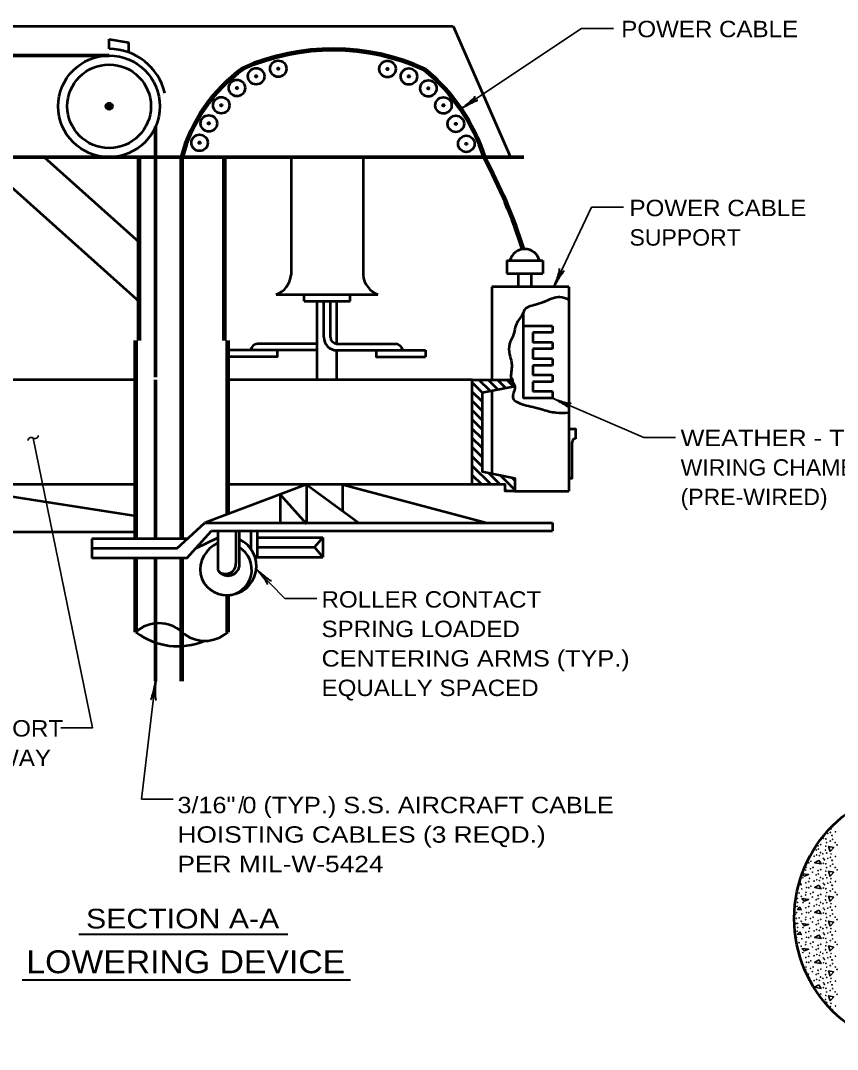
# Model space of a CAD drawing. Extents: x -1 to 679, y 0 to 440.
# Drawn here: x 208.2 to 332.8, y 109.6 to 266.6 of the extents above; entities that cross this region are included whole.
import ezdxf
from ezdxf.enums import TextEntityAlignment as Align

# ---------------------------------------------------------------- set-up
doc = ezdxf.new("R2010")
doc.units = 0
doc.header["$PDMODE"] = 32
doc.header["$PDSIZE"] = 0.5
doc.layers.add('1', color=7, linetype='Continuous', lineweight=35)

msp = doc.modelspace()

# ---------------------------------------------------------------- hatches: boundary and pattern name
at = {"layer": '1'}
for points in [[(247.661, 259.304, 1), (247.411, 259.304, 1)], [(264.325, 259.26, 1), (264.075, 259.26, 1)], [(244.293, 258.151, 1), (244.043, 258.151, 1)], [(267.586, 258.116, 1), (267.336, 258.116, 1)], [(241.357, 256.358, 1), (241.107, 256.358, 1)], [(270.557, 256.295, 1), (270.307, 256.295, 1)], [(222.233, 253.567, 1), (221.233, 253.567, 1)], [(238.965, 253.726, 1), (238.715, 253.726, 1)], [(272.86, 253.701, 1), (272.61, 253.701, 1)], [(237.069, 250.956, 1), (236.819, 250.956, 1)], [(274.748, 250.886, 1), (274.498, 250.886, 1)], [(235.657, 247.993, 1), (235.407, 247.993, 1)], [(276.345, 247.833, 1), (276.095, 247.833, 1)]]:
    msp.add_hatch(color=256, dxfattribs=at).paths.add_polyline_path(points)

# ---------------------------------------------------------------- linework, layer by layer
at = {"layer": '1', "lineweight": 53}
for p, q in [((194.233, 265.817), (274.233, 265.817)), ((274.233, 265.817), (282.983, 245.817)), ((221.733, 262.317), (221.733, 263.817)), ((221.733, 263.817), (224.733, 263.317)), ((224.733, 261.787), (224.733, 263.317)), ((201.721, 245.817), (226.335, 223.749)), ((211.835, 245.817), (226.335, 232.817)), ((249.483, 245.817), (249.483, 227.817)), ((260.483, 245.817), (260.483, 227.817)), ((282.378, 230.022), (287.878, 230.022)), ((282.378, 230.022), (282.378, 228.022)), ((287.878, 230.022), (287.878, 228.022)), ((282.378, 228.022), (287.878, 228.022)), ((284.128, 228.022), (284.128, 226.022)), ((286.128, 228.022), (286.128, 226.022)), ((247.233, 224.817), (262.733, 224.817)), ((251.483, 223.817), (251.483, 224.817)), ((258.483, 223.817), (258.483, 224.817)), ((291.878, 226.022), (280.128, 226.022)), ((280.128, 226.022), (280.128, 211.817)), ((291.878, 226.022), (291.878, 194.817)), ((251.483, 223.817), (258.483, 223.817)), ((253.483, 211.817), (253.483, 223.817)), ((254.483, 218.317), (254.483, 223.817)), ((255.483, 218.317), (255.483, 223.817)), ((256.483, 217.317), (256.483, 223.817)), ((284.878, 222.022), (284.878, 209.022)), ((289.378, 220.022), (284.878, 220.022)), ((289.378, 220.022), (289.378, 219.022)), ((289.378, 219.022), (286.378, 219.022)), ((286.378, 219.022), (286.378, 217.522)), ((253.483, 217.317), (244.353, 217.317)), ((256.483, 217.317), (265.483, 217.317)), ((289.378, 217.522), (286.378, 217.522)), ((289.378, 217.522), (289.378, 216.522)), ((239.853, 216.317), (239.853, 215.317)), ((253.483, 216.317), (239.853, 216.317)), ((256.483, 216.317), (269.983, 216.317)), ((256.483, 211.817), (256.483, 216.317)), ((269.983, 216.317), (269.983, 215.317)), ((289.378, 216.522), (286.378, 216.522)), ((286.378, 216.522), (286.378, 215.022)), ((289.378, 215.022), (286.378, 215.022)), ((289.378, 214.022), (286.378, 214.022)), ((286.378, 214.022), (286.378, 212.522)), ((289.378, 215.022), (289.378, 214.022)), ((289.378, 212.522), (286.378, 212.522)), ((289.378, 212.522), (289.378, 211.522)), ((225.835, 211.817), (196.233, 211.817)), ((277.128, 211.817), (239.835, 211.817)), ((278.707, 209.833), (277.128, 211.412)), ((279.886, 210.069), (278.137, 211.817)), ((281.064, 210.304), (279.552, 211.817)), ((282.243, 210.54), (280.966, 211.817)), ((283.421, 210.776), (282.38, 211.817)), ((289.378, 211.522), (286.378, 211.522)), ((286.378, 211.522), (286.378, 210.022)), ((278.628, 208.498), (277.128, 209.998)), ((280.128, 210.117), (280.128, 197.517)), ((289.378, 209.022), (284.878, 209.022)), ((289.378, 210.022), (286.378, 210.022)), ((289.378, 210.022), (289.378, 209.022)), ((278.628, 207.084), (277.128, 208.584)), ((278.628, 205.67), (277.128, 207.17)), ((278.628, 204.256), (277.128, 205.756)), ((278.628, 202.841), (277.128, 204.341)), ((278.628, 201.427), (277.128, 202.927)), ((278.628, 200.013), (277.128, 201.513)), ((278.628, 198.599), (277.128, 200.099)), ((279.995, 195.817), (277.128, 198.684)), ((278.581, 195.817), (277.128, 197.27)), ((281.409, 195.817), (279.605, 197.622)), ((283.628, 195.013), (281.373, 197.268)), ((283.628, 196.427), (283.14, 196.915)), ((195.233, 195.817), (225.835, 191.067)), ((225.835, 195.817), (196.233, 195.817)), ((251.835, 195.817), (236.335, 190.005)), ((277.128, 195.817), (239.835, 195.817)), ((251.835, 195.817), (251.835, 189.817)), ((251.835, 195.817), (259.828, 190.005)), ((257.335, 195.817), (257.335, 191.817)), ((257.335, 195.817), (279.328, 190.005)), ((277.167, 195.817), (277.128, 195.856)), ((282.409, 194.817), (282.128, 195.099)), ((283.628, 194.817), (291.878, 194.817)), ((247.835, 194.317), (247.835, 189.817)), ((247.835, 194.317), (251.835, 189.817)), ((225.835, 188.567), (164.733, 188.567)), ((232.085, 186.067), (236.335, 190.005)), ((233.585, 184.567), (237.335, 188.755)), ((236.335, 190.005), (289.378, 190.005)), ((237.335, 188.755), (289.378, 188.755)), ((238.335, 188.755), (238.335, 182.755)), ((241.085, 188.755), (241.085, 183.755)), ((241.585, 188.755), (241.585, 183.255)), ((243.335, 188.755), (243.335, 186.092)), ((244.335, 188.755), (244.335, 184.755)), ((289.378, 190.005), (289.378, 188.755)), ((233.704, 187.567), (219.085, 187.567)), ((219.085, 187.567), (219.085, 184.567)), ((238.335, 187.709), (234.878, 186.01)), ((244.335, 187.755), (254.335, 187.755)), ((254.335, 187.755), (254.335, 184.755)), ((232.085, 186.067), (219.085, 186.067)), ((244.335, 186.255), (253.085, 186.255)), ((233.585, 184.567), (219.085, 184.567)), ((244.016, 184.755), (254.335, 184.755))]:
    msp.add_line(p, q, dxfattribs=at)
at = {"layer": '1'}
for p, q in [((275.388, 253.162), (293.808, 265.43)), ((298.666, 265.43), (293.808, 265.43)), ((289.577, 226.022), (295.324, 238.144)), ((300.181, 238.144), (295.324, 238.144)), ((289.378, 209.022), (303.279, 203.025)), ((308.137, 203.025), (303.279, 203.025)), ((244.191, 182.927), (248.548, 178.457)), ((253.405, 178.457), (248.548, 178.457)), ((228.835, 165.817), (226.651, 147.826)), ((231.508, 147.826), (226.651, 147.826)), ((327.108, 135.18), (327.029, 135.097))]:
    msp.add_line(p, q, dxfattribs=at)
at = {"layer": '1', "lineweight": 70}
for p, q in [((200.233, 261.317), (221.733, 261.317)), ((228.835, 212.197), (228.835, 250.466)), ((239.335, 245.817), (284.983, 245.817)), ((228.835, 187.567), (228.835, 211.815)), ((228.835, 165.817), (228.835, 184.567))]:
    msp.add_line(p, q, dxfattribs=at)
at = {"layer": '1', "lineweight": 200}
for p, q in [((226.335, 217.817), (226.335, 245.817)), ((232.835, 187.567), (232.835, 245.817)), ((239.335, 217.817), (239.335, 245.817)), ((225.835, 187.567), (225.835, 217.817)), ((239.835, 191.317), (239.835, 217.817)), ((225.835, 173.317), (225.835, 184.567)), ((232.835, 165.817), (232.835, 184.567)), ((239.835, 173.317), (239.835, 178.92))]:
    msp.add_line(p, q, dxfattribs=at)
at = {"layer": '1', "lineweight": 40}
for p, q in [((217.135, 127.196), (248.977, 127.196)), ((208.484, 120.206), (258.561, 120.206))]:
    msp.add_line(p, q, dxfattribs=at)
at = {"layer": '1', "lineweight": 70}
msp.add_lwpolyline([(183.483, 245.817), (228.835, 245.817), (239.335, 245.817)], dxfattribs=at)
at = {"layer": '1', "lineweight": 53}
for points in [[(247.353, 216.317), (247.353, 215.317), (239.853, 215.317)], [(262.483, 216.317), (262.483, 215.317), (269.983, 215.317)], [(277.128, 195.817), (277.128, 211.817), (283.128, 211.817)], [(283.628, 210.817), (278.628, 209.817), (278.628, 197.817), (283.628, 196.817), (283.628, 194.817), (282.128, 194.817), (282.128, 195.817), (277.128, 195.817)], [(291.878, 204.317), (292.878, 204.317), (292.878, 202.817)], [(291.878, 196.817), (292.378, 196.817), (292.378, 202.317)], [(254.335, 187.755), (253.085, 186.255), (254.335, 184.755)]]:
    msp.add_lwpolyline(points, dxfattribs=at)
at = {"layer": '1'}
for points in [[(210.138, 202.928), (219.214, 158.699), (214.356, 158.699)], [(331.728, 139.8), (331.488, 140.6), (332.268, 140.44), (331.708, 139.84)], [(330.008, 138.46), (329.348, 138.1), (330.328, 137.92), (329.968, 138.48)], [(331.728, 136), (331.488, 136.8), (332.268, 136.64), (331.708, 136.04)], [(326.94, 134.765), (327.308, 134.74), (327.108, 135.14)], [(327.454, 136.412), (328.428, 136.3), (327.748, 136.06), (327.438, 136.37)], [(330.008, 134.66), (329.348, 134.3), (330.328, 134.12), (329.968, 134.68)], [(331.728, 132.2), (331.488, 133), (332.268, 132.84), (331.708, 132.24)], [(327.108, 131.38), (326.728, 130.98), (327.308, 130.94), (327.108, 131.34)], [(330.008, 130.86), (329.348, 130.5), (330.328, 130.32), (329.968, 130.88)], [(331.728, 128.4), (331.488, 129.2), (332.268, 129.04), (331.708, 128.44)], [(327.108, 127.58), (326.728, 127.18), (327.308, 127.14), (327.108, 127.54)], [(330.008, 127.06), (329.348, 126.7), (330.328, 126.52), (329.968, 127.08)], [(331.728, 124.6), (331.488, 125.4), (332.268, 125.24), (331.708, 124.64)], [(327.247, 123.344), (327.308, 123.34), (327.157, 123.641)], [(330.008, 123.26), (329.348, 122.9), (330.328, 122.72), (329.968, 123.28)], [(328.138, 121.133), (328.428, 121.1), (328.197, 121.018)], [(331.728, 120.8), (331.488, 121.6), (332.268, 121.44), (331.708, 120.84)], [(330.008, 119.46), (329.348, 119.1), (330.328, 118.92), (329.968, 119.48)], [(331.728, 117), (331.488, 117.8), (332.268, 117.64), (331.708, 117.04)]]:
    msp.add_lwpolyline(points, dxfattribs=at)
for points in [[(327.388, 132.62), (328.428, 132.5), (327.748, 132.26)], [(327.388, 128.82), (328.428, 128.7), (327.748, 128.46)], [(327.388, 125.02), (328.428, 124.9), (327.748, 124.66)]]:
    msp.add_lwpolyline(points, close=True, dxfattribs=at)
at = {"layer": '1', "lineweight": 53}
for centre, radius in [((221.733, 253.567), 7.75), ((221.733, 253.567), 6.375), ((244.168, 258.151), 1.25), ((247.536, 259.304), 1.25), ((247.536, 259.304), 0.125), ((264.2, 259.26), 1.25), ((264.2, 259.26), 0.125), ((267.461, 258.116), 1.25), ((241.232, 256.358), 1.25), ((244.168, 258.151), 0.125), ((267.461, 258.116), 0.125), ((241.232, 256.358), 0.125), ((270.432, 256.295), 1.25), ((270.432, 256.295), 0.125), ((238.84, 253.726), 1.25), ((272.735, 253.701), 1.25), ((221.733, 253.567), 0.5), ((238.84, 253.726), 0.125), ((272.735, 253.701), 0.125), ((236.944, 250.956), 1.25), ((274.623, 250.886), 1.25), ((236.944, 250.956), 0.125), ((274.623, 250.886), 0.125), ((235.532, 247.993), 1.25), ((276.22, 247.833), 1.25), ((235.532, 247.993), 0.125), ((276.22, 247.833), 0.125), ((346.236, 129.608), 20)]:
    msp.add_circle(centre, radius, dxfattribs=at)
at = {"layer": '1'}
for centre in [(331.849, 143.256), (330.683, 141.829), (331.067, 141.737), (331.359, 142.572), (331.73, 141.405), (331.756, 142.731), (331.982, 142.267), (332.035, 142.267), (332.101, 141.684), (332.538, 142.837), (329.596, 140.053), (329.874, 140.689), (329.914, 140.199), (330.285, 140.862), (331.014, 140.026), (331.054, 140.623), (331.187, 141.167), (332.499, 141.193), (332.777, 140.822), (328.774, 138.321), (329.265, 139.103), (329.662, 139.297), (330.06, 139.17), (330.259, 139.655), (330.617, 139.456), (330.683, 138.772), (330.842, 138.56), (331.2, 139.602), (331.359, 138.772), (331.756, 138.931), (331.849, 139.456), (331.982, 138.467), (332.035, 138.467), (332.538, 139.037), (327.979, 136.995), (328.032, 137.393), (328.456, 138.083), (328.721, 137.181), (329, 136.664), (329.119, 137.393), (329.874, 136.889), (330.285, 137.062), (330.683, 138.029), (331.054, 136.823), (331.067, 137.937), (331.187, 137.367), (331.73, 137.605), (332.101, 137.884), (332.499, 137.393), (332.777, 137.022), (327.569, 135.802), (328.006, 135.038), (328.456, 135.21), (328.562, 135.723), (329.265, 135.303), (329.596, 136.253), (329.662, 135.497), (329.914, 136.399), (330.06, 135.37), (330.259, 135.855), (330.617, 135.656), (331.014, 136.226), (331.2, 135.802), (331.756, 135.131), (331.849, 135.656), (332.538, 135.237), (326.972, 133.487), (327.396, 134.097), (328.032, 133.593), (328.112, 134.322), (328.456, 134.283), (328.774, 134.521), (329.119, 133.593), (330.683, 134.972), (330.683, 134.229), (330.842, 134.76), (331.067, 134.137), (331.187, 133.567), (331.359, 134.972), (331.73, 133.805), (331.982, 134.667), (332.035, 134.667), (332.101, 134.084), (332.499, 133.593), (326.534, 132.623), (326.76, 132.639), (326.76, 132.042), (327.303, 132.97), (327.569, 132.002), (327.979, 133.195), (328.562, 131.923), (328.721, 133.381), (329, 132.864), (329.596, 132.453), (329.874, 133.089), (329.914, 132.599), (330.259, 132.055), (330.285, 133.262), (331.014, 132.426), (331.054, 133.023), (331.2, 132.002), (332.777, 133.222), (326.381, 130.549), (326.614, 130.469), (326.667, 131.45), (328.006, 131.238), (328.112, 130.522), (328.456, 131.41), (328.456, 130.483), (328.774, 130.721), (329.265, 131.503), (329.662, 131.697), (330.06, 131.57), (330.617, 131.856), (330.683, 131.172), (330.683, 130.429), (330.842, 130.96), (331.067, 130.337), (331.359, 131.172), (331.756, 131.331), (331.849, 131.856), (331.982, 130.867), (332.035, 130.867), (332.538, 131.437), (326.395, 130.231), (326.534, 128.823), (326.554, 129.634), (326.76, 128.839), (326.972, 129.687), (327.303, 129.17), (327.396, 130.297), (327.979, 129.395), (328.032, 129.793), (328.721, 129.581), (329, 129.064), (329.119, 129.793), (329.874, 129.289), (329.914, 128.799), (330.285, 129.462), (331.054, 129.223), (331.187, 129.767), (331.73, 130.005), (332.101, 130.284), (332.499, 129.793), (332.777, 129.422), (326.667, 127.65), (326.76, 128.242), (327.569, 128.202), (328.006, 127.438), (328.456, 127.61), (328.562, 128.123), (329.265, 127.703), (329.596, 128.653), (329.662, 127.897), (330.06, 127.77), (330.259, 128.255), (330.617, 128.056), (330.683, 127.372), (331.014, 128.626), (331.2, 128.202), (331.359, 127.372), (331.756, 127.531), (331.849, 128.056), (332.538, 127.637), (326.614, 126.669), (326.972, 125.887), (327.396, 126.497), (328.032, 125.993), (328.112, 126.722), (328.456, 126.683), (328.721, 125.781), (328.774, 126.921), (329.119, 125.993), (330.285, 125.662), (330.683, 126.629), (330.842, 127.16), (331.067, 126.537), (331.187, 125.967), (331.73, 126.205), (331.982, 127.067), (332.035, 127.067), (332.101, 126.484), (332.499, 125.993), (332.777, 125.622), (327.303, 125.37), (327.569, 124.402), (327.979, 125.595), (328.562, 124.323), (329, 125.264), (329.596, 124.853), (329.662, 124.097), (329.874, 125.489), (329.914, 124.999), (330.259, 124.455), (330.617, 124.256), (331.014, 124.826), (331.054, 125.423), (331.2, 124.402), (331.849, 124.256), (328.006, 123.638), (328.112, 122.922), (328.456, 123.81), (328.456, 122.883), (328.774, 123.121), (329.265, 123.903), (330.06, 123.97), (330.683, 123.572), (330.683, 122.829), (330.842, 123.36), (331.067, 122.737), (331.359, 123.572), (331.756, 123.731), (331.982, 123.267), (332.035, 123.267), (332.101, 122.684), (332.538, 123.837), (327.979, 121.795), (328.032, 122.193), (328.721, 121.981), (329, 121.464), (329.119, 122.193), (329.596, 121.053), (329.874, 121.689), (329.914, 121.199), (330.285, 121.862), (331.014, 121.026), (331.054, 121.623), (331.187, 122.167), (331.73, 122.405), (332.499, 122.193), (332.777, 121.822), (328.562, 120.523), (329.265, 120.103), (329.662, 120.297), (330.06, 120.17), (330.259, 120.655), (330.617, 120.456), (330.683, 119.772), (330.842, 119.56), (331.2, 120.602), (331.359, 119.772), (331.756, 119.931), (331.849, 120.456), (331.982, 119.467), (332.035, 119.467), (332.538, 120.037), (330.285, 118.062), (330.683, 119.029), (331.054, 117.823), (331.067, 118.937), (331.187, 118.367), (331.73, 118.605), (332.101, 118.884), (332.499, 118.393), (332.777, 118.022), (331.014, 117.226), (331.2, 116.802), (331.849, 116.656), (332.538, 116.237), (331.756, 116.131), (331.982, 115.667), (332.035, 115.667)]:
    msp.add_circle(centre, 0.0265, dxfattribs=at)
at = {"layer": '1', "lineweight": 53}
for centre, radius, start, end in [((221.733, 253.567), 8.75, 13.21298, 90), ((285.128, 229.451), 2.321, 14.25003, 165.74997), ((245.99, 228.093), 3.503, 290.77405, 355.48615), ((263.976, 228.093), 3.503, 184.51385, 249.22595), ((256.483, 218.317), 2, 180, 270), ((256.483, 218.317), 1, 180, 270), ((244.55, 216.084), 1.249, 99.06756, 169.23059), ((265.286, 216.084), 1.249, 10.76941, 80.93244), ((292.839, 202.356), 0.463, 85.16169, 184.83831), ((239.511, 182.858), 3.98, 274.66923, 58.59072), ((239.532, 183.745), 1.553, 219.60119, 0.36502), ((239.851, 183.714), 1.794, 212.33384, 345.15848), ((229.335, 169.452), 5.214, 47.83573, 132.16427), ((232.217, 181.616), 10.469, 232.43894, 292.84425), ((236.335, 177.182), 5.214, 227.83573, 312.16427)]:
    msp.add_arc(centre, radius, start, end, dxfattribs=at)
at = {"layer": '1', "lineweight": 200}
for centre, radius, start, end in [((255.869, 228.426), 33.811, 65.5326, 113.9223), ((256.284, 239.614), 24.255, 125.61654, 165.18227), ((251.591, 236.963), 28.788, 17.9133, 50.57589), ((199.037, 203.822), 90.305, 18.02279, 27.71258)]:
    msp.add_arc(centre, radius, start, end, dxfattribs=at)
at = {"layer": '1'}
for centre, radius, start, end in [((209.85, 202.53), 0.49, 54.13935, 179.72998), ((210.425, 203.325), 0.49, 234.13935, 359.72998), ((330.842, 142.36), 0.0265, 266.58029, 15.42037), ((326.302, 127.964), 0.0265, 322.82051, 43.18034), ((326.76, 125.039), 0.0265, 342.53248, 47.46843)]:
    msp.add_arc(centre, radius, start, end, dxfattribs=at)
at = {"layer": '1', "lineweight": 40}
for centre, major_axis, ratio, start_param, end_param in [((276.143, 253.997), (-1.4, -1.12), 0.122415, 0.8963533, 3.1415927), ((276.438, 253.607), (-1.559, -0.827), 0.07063, 3.1407148, 5.41811), ((289.795, 227.126), (-0.624, -1.68), 0.122415, 0.8963533, 3.1415927), ((289.795, 227.126), (-0.624, -1.68), 0.122415, 0.8963533, 3.1415927), ((290.248, 226.944), (0.911, 1.512), 0.07063, 6.2823074, 8.5597026), ((290.248, 226.944), (0.911, 1.512), 0.07063, 6.2823074, 8.5597026), ((290.323, 208.384), (-1.543, 0.857), 0.07063, 3.1407148, 5.41811), ((290.323, 208.384), (-1.543, 0.857), 0.07063, 3.1407148, 5.41811), ((290.489, 208.843), (-1.702, 0.564), 0.122415, 0.8963533, 3.1415927), ((290.489, 208.843), (-1.702, 0.564), 0.122415, 0.8963533, 3.1415927), ((244.822, 181.977), (1.1, -1.38), 0.07063, 6.2823074, 8.5597026), ((244.822, 181.977), (1.1, -1.38), 0.07063, 6.2823074, 8.5597026), ((245.151, 182.338), (-1.358, 1.17), 0.122415, 0.8963533, 3.1415927), ((245.151, 182.338), (-1.358, 1.17), 0.122415, 0.8963533, 3.1415927), ((228.49, 164.73), (-0.386, -1.722), 0.07063, 6.2823074, 8.5597026), ((228.49, 164.73), (-0.386, -1.722), 0.07063, 6.2823074, 8.5597026), ((228.978, 164.7), (0.06, 1.792), 0.122415, 0.8963533, 3.1415927), ((228.978, 164.7), (0.06, 1.792), 0.122415, 0.8963533, 3.1415927)]:
    msp.add_ellipse(centre, major_axis=major_axis, ratio=ratio, start_param=start_param, end_param=end_param, dxfattribs=at)
at = {"layer": '1', "lineweight": 53}
for centre, major_axis, ratio, start_param, end_param in [((240.07, 183.134), (4.092, 1.858), 0.924461, 1.5748771, 4.2621165), ((239.727, 183.413), (4.092, -1.858), 0.992304, 5.1626615, 7.8539816)]:
    msp.add_ellipse(centre, major_axis=major_axis, ratio=ratio, start_param=start_param, end_param=end_param, dxfattribs=at)
msp.add_spline([(291.878, 224.022), (290.48, 224.413), (288.373, 223.838), (286.792, 223.263), (284.972, 222.304), (284.878, 222.022), (283.966, 220.579), (283.343, 218.519), (282.816, 217.321), (282.816, 215.692), (283.103, 214.494), (283.151, 213.775), (283.128, 211.817), (283.628, 210.817), (283.343, 209.559), (283.343, 208.984), (283.822, 208.505), (286.361, 207.69), (287.894, 207.259), (289.857, 206.827), (291.878, 206.817)], degree=3, dxfattribs=at)
at = {"layer": '1'}
msp.add_point((283.128, 211.817), dxfattribs=at)

# ---------------------------------------------------------------- texts
for s, height, width, p in [('POWER CABLE', 2.5, 1.1, (313.339, 264.111)), ('SECTION A-A', 3, 1.15, (232.955, 128.074)), ('LOWERING DEVICE', 3.5, 1.1, (233.431, 121.239))]:
    msp.add_text(s, height=height, dxfattribs=dict(at, width=width)).set_placement(p, align=Align.CENTER)
for s, width, p in [('POWER CABLE', 1.1, (301.109, 236.797)), ('SUPPORT', 1.05, (301.109, 232.297)), ('WEATHER - TIGHT', 1.15, (308.907, 201.691)), ('WIRING CHAMBER', 1.05, (308.907, 197.191)), ('(PRE-WIRED)', 1.05, (308.907, 192.691)), ('ROLLER CONTACT', 1.1, (254.138, 177.046)), ('SPRING LOADED', 1.1, (254.138, 172.546)), ('CENTERING ARMS (TYP.)', 1.15, (254.138, 168.046)), ('EQUALLY SPACED', 1.1, (254.138, 163.546)), ('LUMINAIRE SUPPORT', 1.1, (175.89, 157.371)), ('RING AND WIREWAY', 1.1, (175.89, 152.871)), ('3/16" 0 (TYP.) S.S. AIRCRAFT CABLE', 1.15, (232.159, 145.663)), ('HOISTING CABLES (3 REQD.)', 1.2, (232.159, 141.163)), ('PER MIL-W-5424', 1.2, (232.159, 136.663))]:
    msp.add_text(s, height=2.5, dxfattribs=dict(at, width=width)).set_placement(p)
msp.add_text('/', height=2.5, dxfattribs=at).set_placement((241.886, 145.667), align=Align.CENTER)

doc.saveas('drawing.dxf')
